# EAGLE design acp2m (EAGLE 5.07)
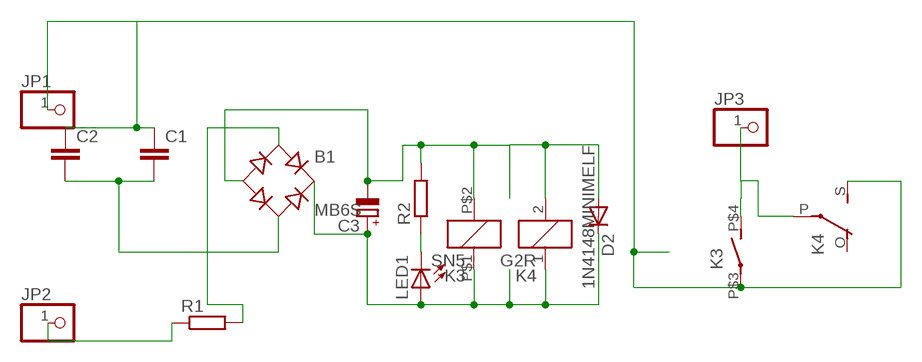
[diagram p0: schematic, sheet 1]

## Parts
B1  MB6S  [SOIC-4]
C1  C-EU150-054X183  [C150-054X183]
C2  C-EU102-043X133  [C102-043X133]
C3  CPOL-EUE2.5-5  [E2,5-5]
D2  1N4148MINIMELF  [MINIMELF]
JP1  PINHD-1X12MM2  [1X2MM2]
JP2  PINHD-1X12MM2  [1X2MM2]
JP3  PINHD-1X12MM2  [1X2MM2]
K3  SN5  [HU]
K4  G2R  [G2R]
LED1  LEDSMT1206  [1206]
R1  R-EU_0204/5  [0204/5]
R2  R-EU_R1206  [R1206]

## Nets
AC1: C1.1 C2.1 JP1.1 K3.P$3(2:P) K4.S(2:S)
AC2: JP2.1 R1.1
ACOUT: JP3.1 K3.P$4(2:S) K4.P(2:P)
MINUS: B1.- C3.- D2.A K3.P$2 K4.2 R2.2
N$4: LED1.C R2.1
PLUS: B1.+ C3.+ D2.C K3.P$1 K4.1 LED1.A
RAC1: B1.~2(AC2) C1.2 C2.2
RAC2: B1.~1(AC1) R1.2
Unconnected: K4.O(2:O)

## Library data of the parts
B1 = rectifier:MB*S: Bridge Rectifier Source: http://www.fairchildsemi.com/ds/MB/MB6S.pdf
C1 C2 = rcl:C-EU: CAPACITOR, European symbol
C3 = rcl:CPOL-EU: POLARIZED CAPACITOR, European symbol
D2 = diode-1:1N4148: DIODE
JP1-JP3 = pinhead:PINHD-1X1: PIN HEADER
K3 = relay:SN*: Slim PCB Relay 1 pole 6 A SCHRACK Source: http://www.schrack.com/.. 5815.pdf
K4 = relay:G2R: RELAY 1 x switch, Omron
LED1 = led:LED: LED
R1 R2 = rcl:R-EU_: RESISTOR, European symbol

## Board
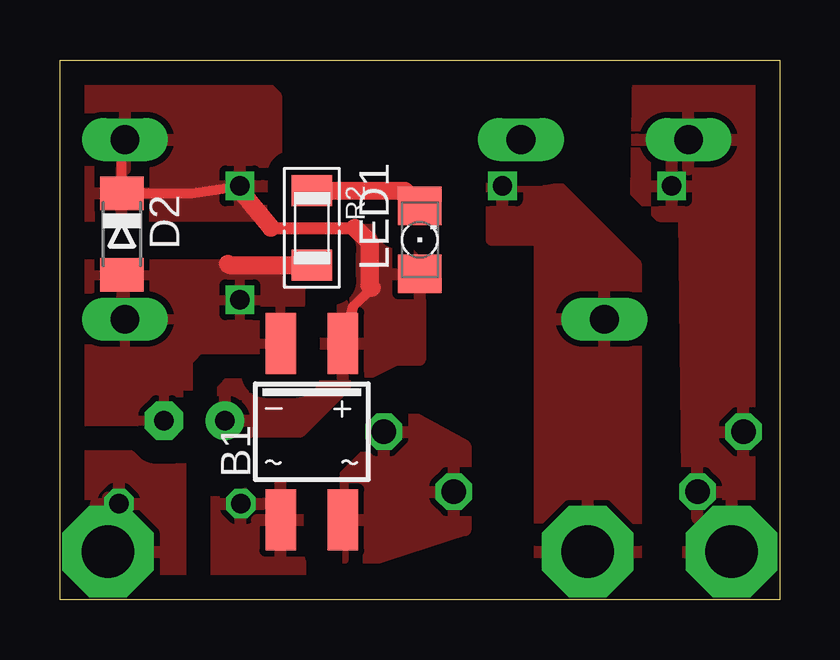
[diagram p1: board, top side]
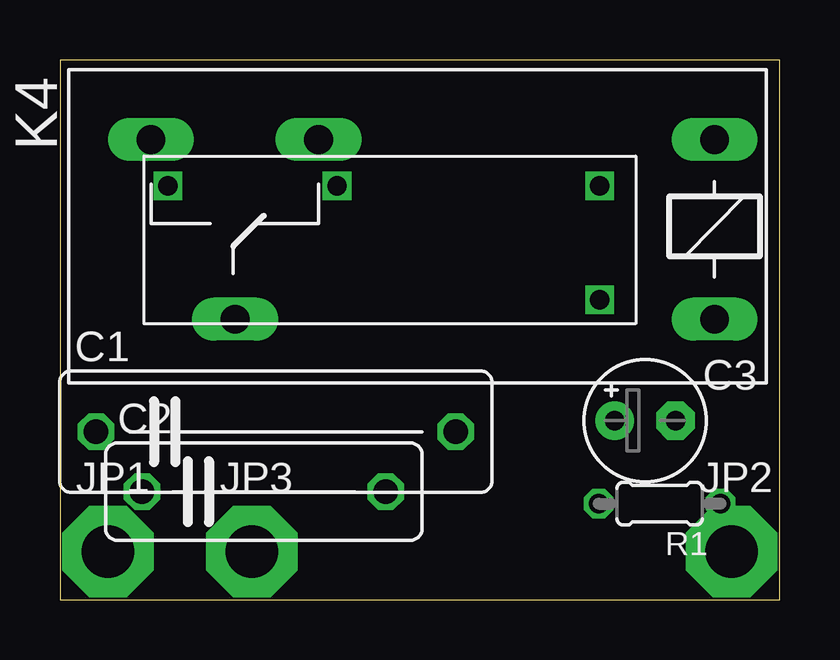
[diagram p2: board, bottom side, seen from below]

Size 30 x 22.5 mm. Coordinates in mm from the lower left corner, seen from the top.
Outline: 30,0 0,0 0,22.5 30,22.5 30,0
Copper layers (1*16): Top 0.035mm / dielectric 1.5mm / Bottom 0.035mm
Design rules "default *": minimum track width 10mil, minimum drill 20mil, track to track 8mil, track to pad 8mil, pad to pad 8mil, via to via 8mil, smd to smd 8mil, copper to edge 40mil, drill to drill 8mil, minimum pad ring 1mil, minimum via ring 8mil, stop-mask expansion 4mil, vias tented up to drill 0mil, thermal gap 10mil

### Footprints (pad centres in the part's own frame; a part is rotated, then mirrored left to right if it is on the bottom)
SOIC-4 = smd 1.27 x 2.54: + 1.3,3.685; - -1.3,3.685; ~1 -1.3,-3.685; ~2 1.3,-3.685
C150-054X183 = drill 1.016 octagon: 1 -7.493,0; 2 7.493,0
C102-043X133 = drill 1.016 octagon: 1 -5.08,0; 2 5.08,0
E2,5-5 = drill 0.813 pad 1.6 round: + -1.27,0 | drill 0.813 pad 1.6 octagon: - 1.27,0
MINIMELF = smd 1.4 x 1.8: A 1.7,0; C -1.7,0
1X2MM2 = drill 2.2 pad 3.81 octagon: 1 0,0
HU = drill 0.8 square: P$1 2.25,-9; P$2 -2.5,-9; P$3 2.25,9; P$4 2.25,1.95
G2R = drill 1.2 pad 1.778 long: 1 -2.54,-3.683; 2 -2.54,3.81; O 13.97,-3.683; P 17.45,3.81; S 20.955,-3.683
1206 = smd 1.6 x 1.803: A -1.422,0; C 1.422,0
0204/5 = drill 0.813 octagon: 1 -2.54,0; 2 2.54,0
R1206 = smd 1.3 x 1.7: 1 -1.55,0; 2 1.55,0

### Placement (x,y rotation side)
B1  10.5,7 0 top
C1  21,7 0 bottom
C2  21.5,4.5 0 bottom
C3  5.61,7.46 0 bottom
D2  2.58,15.24 270 top
JP1  28,2 0 bottom
JP2  2,2 0 bottom
JP3  22,2 0 bottom
K3  16.5,15 90 bottom
K4  5.25,15.5 180 bottom
LED1  15,15 90 top
R1  5,4 180 bottom
R2  10.5,15.5 270 top

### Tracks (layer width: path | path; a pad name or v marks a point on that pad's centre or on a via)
AC1
  pour Top (isolate 0.813): 29.3,22 24.1,22 24,17 25,16 26,16 26.2,-0.2 28,0 30,4 30.2,21.6
AC2
  pour Top (isolate 1): 0,6 5,6 5,0 0,0
ACOUT
  pour Top (isolate 1): 18,18 20,18 24,14 24,0 20,0 20,15 18,15
MINUS
  Top 0.75: R2.2 7.05,13.95 7,14
  pour Top (isolate 1, rank 3): 1,14 10,14 10,10 9,9 7,9 5,7 1,7
N$4
  Top 0.75: R2.1 14.37,17.05 LED1.C
PLUS
  Top 0.406: K4.1 2.58,19.28 D2.C 5.5,16.94 K3.P$1 7.5,17.05 | 12.21,10.21 B1.+ 12.21,12.21 13,13
  Top 0.5: 8.8,15.5 12.3,15.5
  Top 0.75: 7.5,17.05 8.8,15.5 | 12.3,15.5 12.9,14.9 12.9,13.1 13,13
  pour Top (isolate 1, rank 2): 6,7 6,8 7,9 10,9 11,10 11,14 9,16 1,16 1,22 8,22 9,21 9,17 10,16 13,16 15,14 15,10 14,10 12,9 10,7
RAC1
  pour Top (isolate 1.5, rank 3): 11,6 13,8 14,8 16.9,6.4 16.9,2.9 11,1
RAC2
  pour Top (isolate 1, rank 2): 6,4 10,5 10,0 6,0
